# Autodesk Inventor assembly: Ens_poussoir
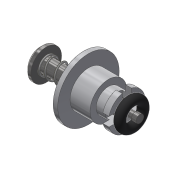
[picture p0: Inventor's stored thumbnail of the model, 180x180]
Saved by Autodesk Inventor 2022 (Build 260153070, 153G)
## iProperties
Created: 2018-06
Part Number: Ens_poussoir
Material: Générique
Document SubType Name: Assembly
Designer: Fabian Perrée
Mass: 5.90054 g
Surface Area: 24.3283 cm^2
Volume: 1.88874 cm^3
Density: 3.12406 g/cm^3
Author: Fabian Perrée
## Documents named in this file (5)
- C:\Users\Fabian\Google Drive\01_Giup\01_Clients\07_ENI\Manuscrit\Fichiers_exercice\Chapitre_06\Exercice_de_fin_de_chapitre\Exercice_fin_de_chapitre_solution\Ens_poussoir.iam
- C:\Users\Fabian\Google Drive\01_Giup\01_Clients\07_ENI\Manuscrit\Fichiers_exercice\Chapitre_06\Exercice_de_fin_de_chapitre\Composants\Guide.ipt
- C:\Users\Fabian\Google Drive\01_Giup\01_Clients\07_ENI\Manuscrit\Fichiers_exercice\Chapitre_06\Exercice_de_fin_de_chapitre\Composants\Poussoir.ipt
- C:\Users\Fabian\Google Drive\01_Giup\01_Clients\07_ENI\Manuscrit\Fichiers_exercice\Chapitre_06\Exercice_de_fin_de_chapitre\Composants\Joint.ipt
- C:\Users\Fabian\Google Drive\01_Giup\01_Clients\07_ENI\Manuscrit\Fichiers_exercice\Chapitre_06\Exercice_de_fin_de_chapitre\Composants\Ressort de compression12.ipt
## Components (4 placed, 4 different names)
1. Guide:1 — Tangente:2, Placage:2
2. Poussoir:1 — Placage:1, Placage:2, Placage:3, Placage:4
3. Joint:1 — Tangente:2, Placage:1
4. Ressort de compression1:1 — Placage:3, Placage:4
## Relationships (5: Mate 4, Tangent 1)
- Tangente:2: Guide:1 ↔ Joint:1
- Placage:1 [Mate]: Poussoir:1 ↔ Joint:1
- Placage:2 [Mate]: Guide:1 ↔ Poussoir:1
- Placage:3 [Mate]: Poussoir:1 ↔ Ressort de compression1:1
- Placage:4 [Mate]: Poussoir:1 ↔ Ressort de compression1:1
